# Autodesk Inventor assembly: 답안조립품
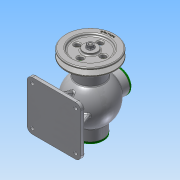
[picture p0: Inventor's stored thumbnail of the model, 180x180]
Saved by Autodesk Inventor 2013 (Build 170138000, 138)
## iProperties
Created: 2018-06
Part Number: 답안조립품
Document SubType Name: Assembly
Designer: Administrator
Author: Administrator
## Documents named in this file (19)
- C:\Users\Administrator\Desktop\480612V1014\답안조립품.iam
- C:\Users\Administrator\Desktop\480612V1014\본체.ipt
- C:\Users\Administrator\Desktop\480612V1014\V-벨트풀리.ipt
- C:\Users\Administrator\Desktop\480612V1014\너트 M8.ipt
- C:\Users\Administrator\Desktop\480612V1014\뒤커버.ipt
- C:\Users\Administrator\Desktop\480612V1014\멈춤링 15x1.ipt
- C:\Users\Administrator\Desktop\480612V1014\멈춤링 35x1.6.ipt
- 멈춤링 35x1.6.ipt
- C:\Users\Administrator\Desktop\480612V1014\베어링 6202.ipt
- 베어링 6202.ipt
- C:\Users\Administrator\Desktop\480612V1014\볼트 M4x12.ipt
- C:\Users\Administrator\Desktop\480612V1014\볼트 M4x16.ipt
- C:\Users\Administrator\Desktop\480612V1014\부시.ipt
- C:\Users\Administrator\Desktop\480612V1014\상부커버.ipt
- C:\Users\Administrator\Desktop\480612V1014\슬라이드.ipt
- C:\Users\Administrator\Desktop\480612V1014\앞커버.ipt
- C:\Users\Administrator\Desktop\480612V1014\오일 실 15 30 7.ipt
- C:\Users\Administrator\Desktop\480612V1014\키 4x4x12.ipt
- C:\Users\Administrator\Desktop\480612V1014\편심축.ipt
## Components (1 placed, 1 different names)
1. V-벨트풀리:1
